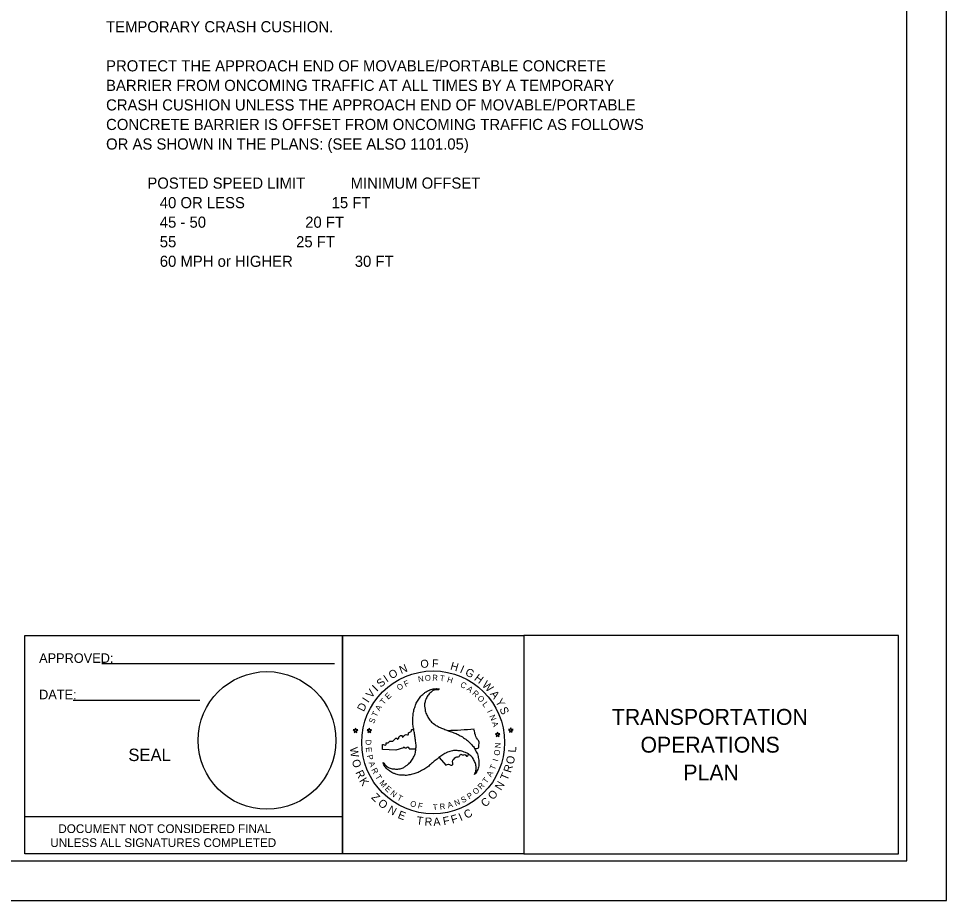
# Model space of a CAD drawing. Extents: x 762655 to 770567, y 650864 to 655190.
# Drawn here: x 769983 to 770567, y 654090 to 654645 of the extents above; entities that cross this region are included whole.
import ezdxf

# ---------------------------------------------------------------- set-up
doc = ezdxf.new("R2010")
doc.units = 0
for name, color, linetype in [('DEV BORDER CELL', 7, 'Continuous'), ('DEV DOT SWIRL SEAL CELL', 7, 'Continuous'), ('DEV PRELIMINARY STAMP CELL', 7, 'Continuous'), ('DEV TRANSPORTATION OPERATIONS PLAN SHEET', 7, 'Continuous'), ('Sheet Sticker Exception Certification CELL', 7, 'Continuous'), ('Text', 7, 'Continuous')]:
    doc.layers.add(name, color=color, linetype=linetype)

msp = doc.modelspace()

# ---------------------------------------------------------------- linework, layer by layer
at = {"layer": 'DEV BORDER CELL'}
for p, q in [((770035.35, 654238.93), (770181.69, 654238.93)), ((770186.84, 654233.11), (770186.84, 654119.11)), ((770017.23, 654215.85), (770097.02, 654215.85))]:
    msp.add_line(p, q, dxfattribs=at)
for points in [[(769986.8, 654256.61), (770186.84, 654256.61), (770186.84, 654119.11), (769986.8, 654119.11)], [(770186.84, 654256.61), (770300.84, 654256.61), (770300.84, 654119.11), (770186.84, 654119.11)], [(770536.84, 654256.61), (770300.84, 654256.61), (770300.84, 654119.11), (770536.84, 654119.11)]]:
    msp.add_lwpolyline(points, close=True, dxfattribs=at)
msp.add_circle((770139.24, 654190.52), 43.34, dxfattribs=at)
at = {"layer": 'DEV DOT SWIRL SEAL CELL'}
for p, q in [((770193.57, 654197.27), (770194.45, 654196.63)), ((770194.65, 654197.27), (770193.57, 654197.27)), ((770194.45, 654196.63), (770194.13, 654195.58)), ((770194.13, 654195.58), (770194.97, 654196.23)), ((770194.97, 654198.27), (770194.65, 654197.27)), ((770195.33, 654197.27), (770194.97, 654198.27)), ((770194.97, 654196.23), (770195.86, 654195.58)), ((770194.97, 654196.23), (770195.85, 654195.58)), ((770196.41, 654197.27), (770195.33, 654197.27)), ((770195.53, 654196.63), (770196.42, 654197.27)), ((770195.53, 654196.63), (770196.41, 654197.27)), ((770195.86, 654195.58), (770195.53, 654196.63)), ((770195.85, 654195.58), (770195.53, 654196.63)), ((770203.33, 654197.26), (770202.24, 654197.26)), ((770202.24, 654197.26), (770203.13, 654196.61)), ((770203.13, 654196.61), (770202.81, 654195.57)), ((770202.81, 654195.57), (770203.65, 654196.21)), ((770203.65, 654198.26), (770203.33, 654197.26)), ((770204.01, 654197.26), (770203.65, 654198.26)), ((770203.65, 654196.21), (770204.53, 654195.57)), ((770205.09, 654197.26), (770204.01, 654197.26)), ((770204.21, 654196.61), (770205.09, 654197.26)), ((770204.53, 654195.57), (770204.21, 654196.61)), ((770292.37, 654197.41), (770291.29, 654197.41)), ((770291.29, 654197.41), (770292.17, 654196.77)), ((770292.17, 654196.77), (770291.85, 654195.73)), ((770291.85, 654195.73), (770292.69, 654196.37)), ((770292.69, 654198.41), (770292.37, 654197.41)), ((770293.06, 654197.41), (770292.69, 654198.41)), ((770292.69, 654196.37), (770293.58, 654195.73)), ((770294.14, 654197.41), (770293.06, 654197.41)), ((770293.26, 654196.77), (770294.14, 654197.41)), ((770293.58, 654195.73), (770293.26, 654196.77)), ((770284.1, 654194.77), (770283.01, 654194.77)), ((770283.01, 654194.77), (770283.89, 654194.13)), ((770283.89, 654194.13), (770283.57, 654193.08)), ((770283.57, 654193.08), (770284.42, 654193.72)), ((770284.42, 654195.77), (770284.1, 654194.77)), ((770284.78, 654194.77), (770284.42, 654195.77)), ((770284.42, 654193.72), (770285.3, 654193.08)), ((770285.86, 654194.77), (770284.78, 654194.77)), ((770284.98, 654194.13), (770285.86, 654194.77)), ((770285.3, 654193.08), (770284.98, 654194.13)), ((770211.89, 654184.83), (770211.98, 654187.48)), ((770220.28, 654184.51), (770211.89, 654184.83)), ((770225.09, 654185.93), (770220.28, 654184.51)), ((770228.79, 654185.36), (770233, 654185.33)), ((770247.54, 654179.74), (770251.85, 654175.08))]:
    msp.add_line(p, q, dxfattribs=at)
for start, end in [(265.67849, 265.97623), (271.20351, 275.32356)]:
    msp.add_arc((770247.93, 654430.01), 233.19, start, end, dxfattribs=at)
for points in [[(770212.3, 654176.71), (770214.05, 654174.7), (770216.22, 654173.31), (770218.72, 654172.66), (770221.54, 654172.5), (770224.41, 654173.17), (770226.32, 654174.14), (770227.12, 654174.78), (770228.52, 654175.88), (770229.51, 654176.95), (770231.17, 654179.32), (770232.46, 654182.11), (770233, 654185.3), (770233.03, 654185.57), (770233, 654188.58), (770232.6, 654191.61), (770232.17, 654194.54), (770231.63, 654197.57), (770231.15, 654200.58), (770231.09, 654203.51), (770231.28, 654206.86), (770231.77, 654209.73), (770232.71, 654212.69), (770233.22, 654214.08), (770233.91, 654215.21), (770235.66, 654217.86), (770237.94, 654220.01), (770239.44, 654221.14), (770240.87, 654221.89), (770241.11, 654222.03), (770243.95, 654222.94), (770246.74, 654223.05), (770247.69, 654222.8)], [(770247.76, 654222.89), (770247.69, 654222.8), (770245.11, 654222.32), (770242.77, 654221.12), (770240.97, 654219.29), (770239.44, 654216.95), (770238.58, 654214.11), (770238.45, 654211.99), (770238.64, 654210.97), (770238.88, 654209.2), (770239.28, 654207.8), (770240.55, 654205.2), (770242.29, 654202.67), (770244.81, 654200.61), (770245.03, 654200.44), (770247.6, 654198.97), (770250.48, 654197.79), (770253.21, 654196.71), (770256.09, 654195.67), (770258.93, 654194.54), (770261.51, 654193.14), (770264.33, 654191.32), (770266.55, 654189.47), (770268.65, 654187.19), (770269.62, 654186.03), (770270.23, 654184.85), (770271.68, 654182.03), (770272.38, 654178.97), (770272.62, 654177.09), (770272.57, 654175.48), (770272.57, 654175.21), (770271.9, 654172.29), (770270.58, 654169.82), (770269.94, 654169.15)], [(770211.98, 654187.48), (770211.89, 654187.74), (770212.34, 654188.02), (770213.59, 654187.51), (770214.21, 654188.05), (770214.18, 654188.58), (770214.69, 654189.12), (770215.54, 654188.95), (770216.3, 654189.91), (770217, 654190.11), (770218.5, 654190.11), (770220.28, 654191.89), (770221.02, 654192), (770221.22, 654191.52), (770221.67, 654191.44), (770222.46, 654192.91), (770222.66, 654193.1), (770224.01, 654193.67), (770224.38, 654193.39), (770224.49, 654192.74), (770224.69, 654192.63), (770225.14, 654192.94), (770225.77, 654193.73), (770226.9, 654194.32), (770228.19, 654194.15), (770228.42, 654195.23), (770229.95, 654196.24), (770230.26, 654196.86), (770230.34, 654197.49)], [(770269.87, 654185.59), (770272.33, 654185.9), (770272.7, 654187.85), (770272.73, 654189.49), (770271.71, 654191.38), (770270.19, 654194.86), (770269.56, 654197.83)], [(770228.79, 654185.36), (770228.45, 654186.01), (770227.77, 654186.21), (770226.84, 654185.73), (770226.16, 654185.76), (770225.4, 654186.32), (770225.09, 654185.93)], [(770269.94, 654169.15), (770270.8, 654171.61), (770270.93, 654174.22), (770270.23, 654176.71), (770268.97, 654179.21), (770266.96, 654181.36), (770265.19, 654182.54), (770264.19, 654182.89), (770262.58, 654183.59), (770261.11, 654183.91), (770258.26, 654184.15), (770255.17, 654183.88), (770252.14, 654182.73), (770251.9, 654182.62), (770249.32, 654181.09), (770246.88, 654179.24), (770244.54, 654177.41), (770242.21, 654175.43), (770239.82, 654173.49), (770237.32, 654171.99), (770234.32, 654170.46), (770231.6, 654169.47), (770228.6, 654168.79), (770227.09, 654168.53), (770225.78, 654168.58), (770222.64, 654168.74), (770219.61, 654169.65), (770217.89, 654170.38), (770216.52, 654171.26), (770216.28, 654171.4), (770214.08, 654173.41), (770212.6, 654175.77), (770212.3, 654176.71)], [(770251.85, 654175.08), (770253.54, 654175.58), (770254.95, 654175.05), (770255.63, 654174.94), (770256.2, 654175.36), (770256.03, 654177.48), (770256.51, 654178.47), (770258.8, 654180.16), (770260.21, 654180.47), (770261.26, 654181.78), (770261.68, 654181.75), (770262.33, 654181.38), (770263.77, 654181.66), (770264.93, 654180.73), (770265.61, 654180.78), (770266.15, 654181.85)]]:
    msp.add_spline(points, degree=3, dxfattribs=at)
at = {"layer": 'DEV TRANSPORTATION OPERATIONS PLAN SHEET'}
msp.add_lwpolyline([(770541.99, 655164.84), (769041.98, 655164.84), (769041.98, 654114.84), (770541.99, 654114.84)], close=True, dxfattribs=at)
at = {"layer": 'Sheet Sticker Exception Certification CELL'}
for p, q in [((769986.8, 654119.11), (769986.8, 654142.61)), ((769986.8, 654142.61), (770186.84, 654142.61)), ((770186.84, 654142.59), (770186.84, 654119.09)), ((770186.84, 654119.11), (769986.8, 654119.11))]:
    msp.add_line(p, q, dxfattribs=at)
at = {"layer": 'Text'}
msp.add_lwpolyline([(768878.99, 654089.84), (770566.99, 654089.84), (770566.99, 655189.84), (768878.99, 655189.84)], close=True, dxfattribs=at)
msp.add_circle((770243.84, 654189.31), 44.97, dxfattribs=at)

# ---------------------------------------------------------------- texts
at = {"layer": 'DEV BORDER CELL'}
for s, p in [('APPROVED:  ', (769995.77, 654239.36)), ('DATE:  ', (769995.77, 654216.45))]:
    msp.add_text(s, height=6, dxfattribs=at).set_placement(p)
at = {"layer": 'DEV DOT SWIRL SEAL CELL'}
for s, height, rotation, p in [('N', 5.04, 21.58606, (770223.69, 654232.31)), ('O', 5.04, 5.76495, (770236.09, 654236.04)), ('F', 5.04, 357.25753, (770243.05, 654236.6)), ('H', 5.04, 343.45399, (770254.28, 654235.3)), ('I', 5.04, 335.80403, (770260.27, 654233.44)), ('I', 5.04, 34.38082, (770214.71, 654226.9)), ('O', 5.04, 30.09348, (770217.58, 654228.94)), ('N', 3.63, 9.02265, (770234.61, 654227.26)), ('O', 3.63, 3.94457, (770238.76, 654227.97)), ('R', 3.63, 358.86648, (770243.24, 654228.25)), ('G', 5.04, 331.5167, (770263.51, 654232.05)), ('H', 5.04, 323.46323, (770269.26, 654228.8)), ('I', 5.04, 44.87218, (770208.39, 654221.07)), ('S', 5.04, 40.58484, (770210.84, 654223.59)), ('O', 3.63, 29.33499, (770222.18, 654221.79)), ('F', 3.63, 24.25691, (770226.39, 654224.14)), ('H', 3.63, 343.63223, (770252.31, 654227.39)), ('C', 3.63, 333.47606, (770260.55, 654224.47)), ('W', 5.04, 315.81328, (770274.25, 654225)), ('V', 5.04, 51.5806, (770204.95, 654216.77)), ('E', 3.63, 44.56924, (770215.57, 654216.1)), ('A', 3.63, 323.31989, (770264.64, 654222.34)), ('R', 3.63, 318.24181, (770268.14, 654219.79)), ('A', 5.04, 306.77624, (770279.44, 654219.7)), ('D', 5.04, 63.45904, (770200.16, 654208.29)), ('I', 5.04, 55.86794, (770203.02, 654213.83)), ('T', 3.63, 49.64733, (770212.72, 654212.79)), ('O', 3.63, 313.16372, (770271.35, 654216.88)), ('L', 3.63, 308.08564, (770274.56, 654213.2)), ('Y', 5.04, 299.74838, (770282.85, 654215.05)), ('T', 3.63, 64.88158, (770208.22, 654205.02)), ('A', 3.63, 59.8035, (770210.15, 654208.81)), ('I', 3.63, 297.92947, (770277.61, 654208.7)), ('S', 5.04, 293.2249, (770285.49, 654210.39)), ('S', 3.63, 69.95967, (770206.63, 654200.87)), ('N', 3.63, 292.85138, (770279.13, 654205.79)), ('A', 3.63, 287.7733, (770280.73, 654201.74)), ('D', 3.63, 270.27201, (770201.28, 654191.02)), ('E', 3.63, 275.35009, (770201.4, 654186.15)), ('O', 3.63, 82.92689, (770285.65, 654180.78)), ('N', 3.63, 87.73296, (770286.28, 654185.65)), ('P', 3.63, 285.50626, (770202.01, 654180.95)), ('I', 3.63, 72.77072, (770284.57, 654177.03)), ('A', 3.63, 290.58434, (770203.21, 654176.49)), ('R', 3.63, 295.66243, (770204.88, 654172.16)), ('T', 3.63, 67.69263, (770282.57, 654171.64)), ('T', 3.63, 300.74051, (770207.16, 654167.75)), ('T', 3.63, 52.45838, (770277.39, 654163.15)), ('A', 3.63, 62.61455, (770280.35, 654167.29)), ('M', 3.63, 310.89668, (770209.78, 654163.66)), ('E', 3.63, 315.97477, (770213.11, 654159.84)), ('R', 3.63, 47.38029, (770274.14, 654159.41)), ('N', 3.63, 321.05285, (770216.53, 654156.68)), ('T', 3.63, 331.20902, (770220.78, 654153.44)), ('S', 3.63, 27.06795, (770262.41, 654151.02)), ('P', 3.63, 32.14604, (770266.53, 654153.33)), ('O', 3.63, 42.30221, (770270.61, 654156.15)), ('O', 3.63, 341.36519, (770228.99, 654149.42)), ('F', 3.63, 346.44327, (770233.91, 654147.94)), ('T', 3.63, 1.67753, (770243.67, 654146.74)), ('R', 3.63, 6.75561, (770248.16, 654146.98)), ('A', 3.63, 16.91178, (770253.42, 654147.76)), ('N', 3.63, 21.98987, (770257.99, 654149.15))]:
    msp.add_text(s, height=height, rotation=rotation, dxfattribs=at).set_placement(p)
at = {"layer": 'DEV PRELIMINARY STAMP CELL'}
msp.add_text('SEAL', height=7.812, dxfattribs=at).set_placement((770051.97, 654177.56))
at = {"layer": 'DEV TRANSPORTATION OPERATIONS PLAN SHEET'}
for s, p in [('TRANSPORTATION', (770356.38, 654200.36)), ('OPERATIONS', (770374.38, 654182.86)), ('PLAN', (770401.38, 654165.36))]:
    msp.add_text(s, height=10, dxfattribs=at).set_placement(p)
at = {"layer": 'Sheet Sticker Exception Certification CELL'}
for s, p in [('DOCUMENT NOT CONSIDERED FINAL', (770007.87, 654132.26)), ('UNLESS ALL SIGNATURES COMPLETED', (770002.8, 654123.46))]:
    msp.add_text(s, height=5.5, dxfattribs=at).set_placement(p)
at = {"layer": 'Text'}
for s, p in [('            TEMPORARY CRASH CUSHION.', (770006.72, 654636.22)), ('            PROTECT THE APPROACH END OF MOVABLE/PORTABLE CONCRETE', (770006.72, 654611.62)), ('            BARRIER FROM ONCOMING TRAFFIC AT ALL TIMES BY A TEMPORARY', (770006.72, 654599.32)), ('            CRASH CUSHION UNLESS THE APPROACH END OF MOVABLE/PORTABLE', (770006.72, 654587.02)), ('            CONCRETE BARRIER IS OFFSET FROM ONCOMING TRAFFIC AS FOLLOWS', (770006.72, 654574.72)), ('            OR AS SHOWN IN THE PLANS: (SEE ALSO 1101.05)', (770006.72, 654562.42)), ('                      POSTED SPEED LIMIT           MINIMUM OFFSET', (770006.72, 654537.82)), ('                         40 OR LESS                     15 FT ', (770006.72, 654525.52)), ('                         45 - 50                        20 FT ', (770006.72, 654513.22)), ('                         55                             25 FT ', (770006.72, 654500.92)), ('                         60 MPH or HIGHER               30 FT ', (770006.72, 654488.62))]:
    msp.add_text(s, height=7, dxfattribs=at).set_placement(p)
for s, height, rotation, p in [('T', 3.63, 353.7884, (770247.87, 654228.02)), ('W', 5.04, 278.14998, (770191.35, 654185.94)), ('L', 5.04, 87.42899, (770296.03, 654182.86)), ('O', 5.04, 287.11471, (770192.52, 654177.8)), ('O', 5.04, 78.98964, (770294.52, 654175.27)), ('R', 5.04, 72.75186, (770292.7, 654169.85)), ('R', 5.04, 295.55406, (770194.76, 654170.4)), ('K', 5.04, 301.79184, (770197.11, 654165.18)), ('T', 5.04, 66.88101, (770290.45, 654164.95)), ('N', 5.04, 58.89198, (770286.61, 654158.71)), ('Z', 5.04, 316.16875, (770204.57, 654154.33)), ('O', 5.04, 50.45263, (770281.66, 654152.76)), ('O', 5.04, 322.52328, (770208.68, 654150.2)), ('N', 5.04, 330.96263, (770214.8, 654145.46)), ('C', 5.04, 43.08071, (770276.66, 654148.21)), ('E', 5.04, 338.95166, (770221.18, 654141.85)), ('F', 5.04, 17.76266, (770255.93, 654138.13)), ('I', 5.04, 23.75026, (770261.2, 654139.67)), ('C', 5.04, 28.0033, (770264.83, 654141.09)), ('T', 5.04, 352.69479, (770233.1, 654137.83)), ('R', 5.04, 358.56564, (770238.42, 654137)), ('A', 5.04, 4.80342, (770244.14, 654136.72)), ('F', 5.04, 11.77506, (770250.52, 654137.15))]:
    msp.add_text(s, height=height, rotation=rotation, dxfattribs=at).set_placement(p)

doc.saveas('drawing.dxf')
